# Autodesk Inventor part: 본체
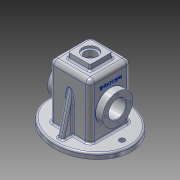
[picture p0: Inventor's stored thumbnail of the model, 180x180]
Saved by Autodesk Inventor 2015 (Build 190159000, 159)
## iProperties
Created: 2017-07
Part Number: 본체
Material: 알루미늄 6061
Document SubType Name: Modeling
Designer: Admin
Density: 2.7 g/cm^3
Appearance: 알루미늄 - 평지
Mass: 893.274 g
Surface Area: 987.904 cm^2
Volume: 330.842 cm^3
Author: Admin
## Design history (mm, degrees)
sketch "스케치1"
  geometry: L1 (-75, 65)-(75, 65); L2 (75, 65)-(75, -65); L3 (75, -65)-(-75, -65); L4 (-75, -65)-(-75, 65); L5 (-75, 65)-(75, -65); L6 (75, 65)-(-75, -65); 1 further point
  constraints: 12 end point, 2 midpoint, 2 parallel, 1 horizontal, 1 perpendicular
  dimensions: "d0" = 150 distance of L2.end L3.end; "d1" = 130 distance of L1.end L2.end
extrude "돌출1" new body sketch "스케치1" distance "d2" = 10; taper "d3" = 0 deg
sketch "스케치2" dims "d7" = 65, "d123" = 75
  geometry: L1 (75, 65)-(-75, 65) reference; L2 (-75, 65)-(-75, -65) reference; L3 (-75, -65)-(75, -65) reference; L4 (75, -65)-(75, 65) reference; L5 (-75, 65)-(-75, -65) reference; L6 (-75, -65)-(-75, 65) reference; 10 further points; 1 other entity
  constraints: 8 midpoint, 4 horizontal alignment, 3 coincident, 1 horizontal, 1 vertical alignment, 2 other
extrude "돌출2" cut sketch "스케치2" distance "d8" = 10; taper "d9" = 0 deg
sketch "스케치3"
  geometry: L1 (-75, 0)-(75, 0) reference; L2 (37, 110)-(-37, 110); L3 (-37, 110)-(-37, 10); L4 (37, 10)-(37, 110); L5 (75, 10)-(-75, 10) reference; 3 further points
  constraints: 6 end point, 2 midpoint, 2 point on line, 1 horizontal, 1 parallel, 1 perpendicular, 1 vertical alignment
  dimensions: "d10" = 74 distance of L2.start L2.end; "d11" = 110 distance between parallel lines of L1 L2
extrude "돌출3" join sketch "스케치3" stored distance "d13" = 74; taper "d14" = 0 deg
sketch "스케치4"
  geometry: L1 (-32, 0)-(-32, 105); L2 (32, 105)-(32, 0); L3 (-32, 0)-(32, 0); L4 (-37, 110)-(37, 110) reference; L5 (-37, 10)-(-37, 110) reference; L6 (37, 110)-(37, 10) reference; L7 (-32, 105)-(32, 105); 5 further points
  constraints: 8 end point, 4 midpoint, 2 vertical alignment, 1 horizontal, 1 horizontal alignment
  dimensions: "d16" = 105 distance of L1.start L1.end; "d17" = 105 distance of L2.start L2.end; "d18" = 64 distance of L1.start L2.end; "d19" = 64 distance of L1.end L2.start; "d125" = 5 distance between parallel lines of L7 L4
extrude "돌출4" cut sketch "스케치4" stored distance "d20" = 64; taper "d21" = 0 deg
node "작업 평면1"
sketch "스케치5"
  geometry: L1 (20, -20)-(-20, -20); L2 (-20, -20)-(-20, 20); L3 (-20, 20)-(20, 20); L4 (20, 20)-(20, -20); L5 (20, -20)-(-20, 20); L6 (-20, -20)-(20, 20); 1 further point
  constraints: 12 end point, 2 midpoint, 2 parallel, 1 horizontal, 1 perpendicular
  dimensions: "d23" = 40 distance of L2.end L3.end; "d24" = 40 distance of L1.end L2.end
extrude "돌출5" join sketch "스케치5" stored distance "d25" = 64; taper "d26" = 5 deg
sketch "스케치6"
  geometry: 2 further points
  constraints: 1 coincident
hole "구멍1" sketch "스케치6" at (0, 0) diameter "d27" = 21; stored, may be unused: countersink angle "d31" = 90 deg, drill point angle "d33" = 0 deg; dims "d28" = 6, "d29" = 28, "d30" = 4, "d32" = 8
sketch "스케치7"
  geometry: L1 (-110, 102)-(-110, -28) reference; C1 r 27.5 at (-55, 37); 2 further points
  constraints: 1 centre point, 1 horizontal alignment, 1 midpoint
  dimensions: "d34" = 55 diameter of C1; "d35" = 55 distance from line of L1 C1.centre
extrude "돌출6" join sketch "스케치7" distance "d36" = 13; taper "d37" = 0 deg
sketch "스케치8"
  geometry: L1 (10, -28)-(10, 102) reference; C1 r 27.5 at (-45, 37); 2 further points
  constraints: 1 centre point, 1 horizontal alignment, 1 midpoint
  dimensions: "d38" = 55 diameter of C1; "d39" = 55 distance from line of L1 C1.centre
extrude "돌출7" join sketch "스케치8" distance "d40" = 13; taper "d41" = 0 deg
sketch "스케치9"
  geometry: L1 (55, -65)-(55, 65) reference; L2 (45, 37)-(45, -37) reference; C1 r 27.5 at (0, 0); 4 further points
  constraints: 2 midpoint, 1 centre point, 1 horizontal alignment, 1 vertical alignment
  dimensions: "d97" = 55 diameter of C1; "d98" = 55 distance from line of L1 C1.centre; "d99" = 22.5 distance of point (0, 22.5) C1.centre
hole "구멍3" sketch "스케치9" at (0, 22.5) diameter "d52" = 3.242; stored, may be unused: countersink angle "d56" = 90 deg, drill point angle "d58" = 118 deg; dims "d53" = 8, "d54" = 28, "d55" = 4, "d57" = 10
sketch "스케치10"
  geometry: L1 (-55, 65)-(-55, -65) reference; C1 r 27.5 at (0, 0); 3 further points
  constraints: 2 horizontal alignment, 1 centre point, 1 midpoint
  dimensions: "d100" = 55 diameter of C1; "d101" = 55 distance from line of L1 C1.centre; "d102" = 22.5 distance of C1.centre point (22.5, 0)
hole "구멍4" sketch "스케치10" at (22.5, 0) diameter "d63" = 3.242; stored, may be unused: countersink angle "d67" = 90 deg, drill point angle "d69" = 118 deg; dims "d64" = 8, "d65" = 28, "d66" = 4, "d68" = 10
sketch "스케치11"
  geometry: C1 r 27.5 at (50, 32) reference; 1 further point
extrude "돌출8" join sketch "스케치11" distance "d73" = 7; taper "d74" = -45 deg
sketch "스케치12"
  geometry: C1 r 27.5 at (55, 32) reference; 1 further point
extrude "돌출9" join sketch "스케치12" distance "d75" = 7; taper "d76" = -45 deg
hole "구멍5" diameter "d79" = 32; stored, may be unused: countersink angle "d83" = 90 deg, drill point angle "d85" = 0 deg; dims "d77" = 10, "d78" = 10, "d80" = 8, "d81" = 28, "d82" = 4, "d84" = 10
sketch "스케치13"
  geometry: L1 (37, 110)-(37, 10) reference; L2 (-37, 10)-(-37, 110) reference; L3 (-55, 10)-(-37, 82.194); L4 (55, 10)-(37, 82.194); L5 (55, 10)-(37, 10); L6 (-55, 10)-(-37, 10); 3 further points
  constraints: 8 end point, 2 point on line, 1 horizontal
  dimensions: "d86" = 10 distance of point (-65, 10) L3.start; "d88" = 10 distance of point (65, 10) L4.start; "d90" = 110 distance of L4.start L3.start; "d126" = 72.19406 vertical distance of L4.start L4.end; "d127" = 72.19406 vertical distance of L3.start L3.end
extrude "돌출10" join sketch "스케치13" stored distance "d95" = 10; taper "d96" = 0 deg
sketch "스케치14"
  geometry: 3 further points
  constraints: 2 horizontal alignment
  dimensions: "d103" = 116 distance of point (58, 0) point (-58, 0); "d104" = 58 distance of point (0, 0) point (-58, 0)
hole "구멍6" sketch "스케치14" at (-58, 0), (58, 0) diameter "d105" = 10; stored, may be unused: countersink angle "d109" = 90 deg, drill point angle "d111" = 0 deg; dims "d106" = 8, "d107" = 28, "d108" = 4, "d110" = 10
fillet "모깎기1" dims "d112" = 8, "d113" = 3, "d114" = 0.5
fillet "모깎기2" dims "d115" = 3
chamfer "모따기1" distance "d116" = 1; stored, may be unused: second distance "d117" = 2, angle "d118" = 45 deg
fillet "모깎기3" dims "d124" = 3
sketch "스케치15"
  geometry: L1 (89, 66)-(0, 66) reference; L2 (-18, 9)-(-18, 49) reference; 2 further points
  constraints: 1 other
  dimensions: "d119" = 37 distance from line of L1 point (12, 29); "d120" = 30 distance from line of point (12, 29) L2
feature "엠보싱1" sketch "스케치15" dims "d0" = 150, "d1" = 130, "d121" = 0.5, "d122" = 0
fillet "모깎기4" dims "d128" = 3
node "솔리드1"
pattern_circular "원형 패턴1" dims angle "d60" = 360 deg
pattern_circular "원형 패턴2" dims angle "d71" = 360 deg
node "투영된 루프1"
